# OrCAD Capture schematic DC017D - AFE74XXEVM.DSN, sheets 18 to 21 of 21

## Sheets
18 SHEET 17 - POWER SUPPLIES: size B; title: POWER SUPPLIES
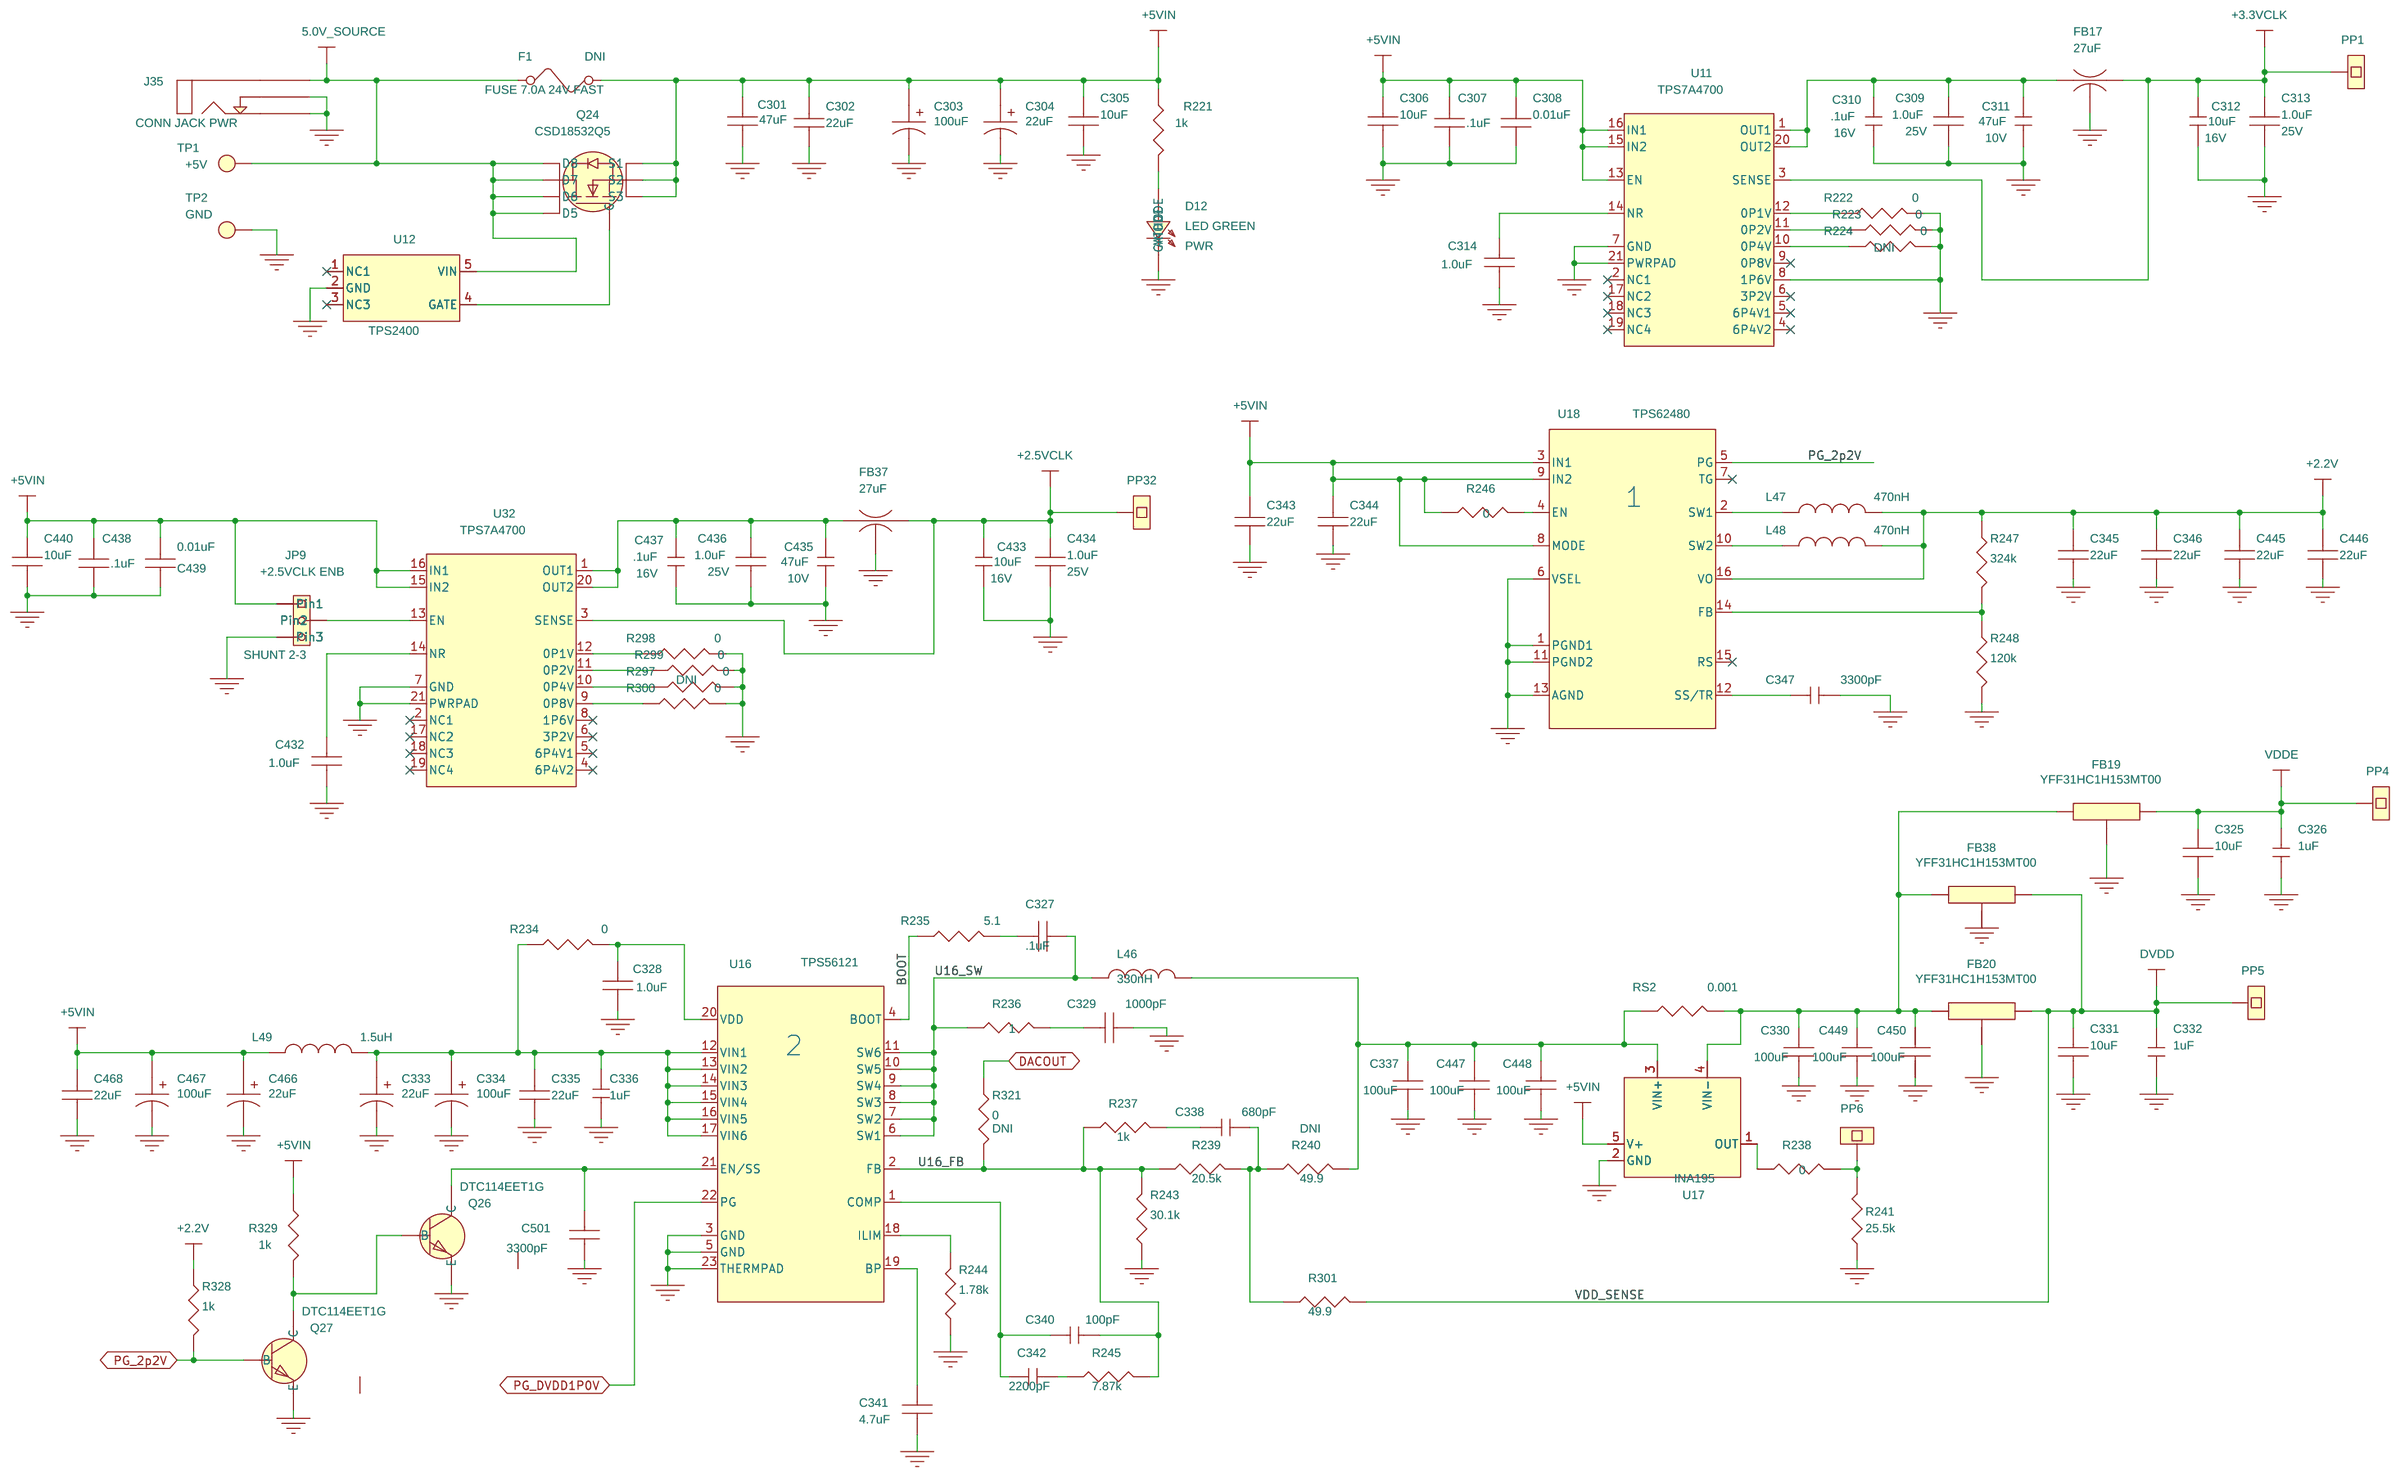
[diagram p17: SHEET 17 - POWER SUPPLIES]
19 SHEET 18 - POWER SUPPLIES: size B; title: POWER SUPPLIES +.9V, +1.8V
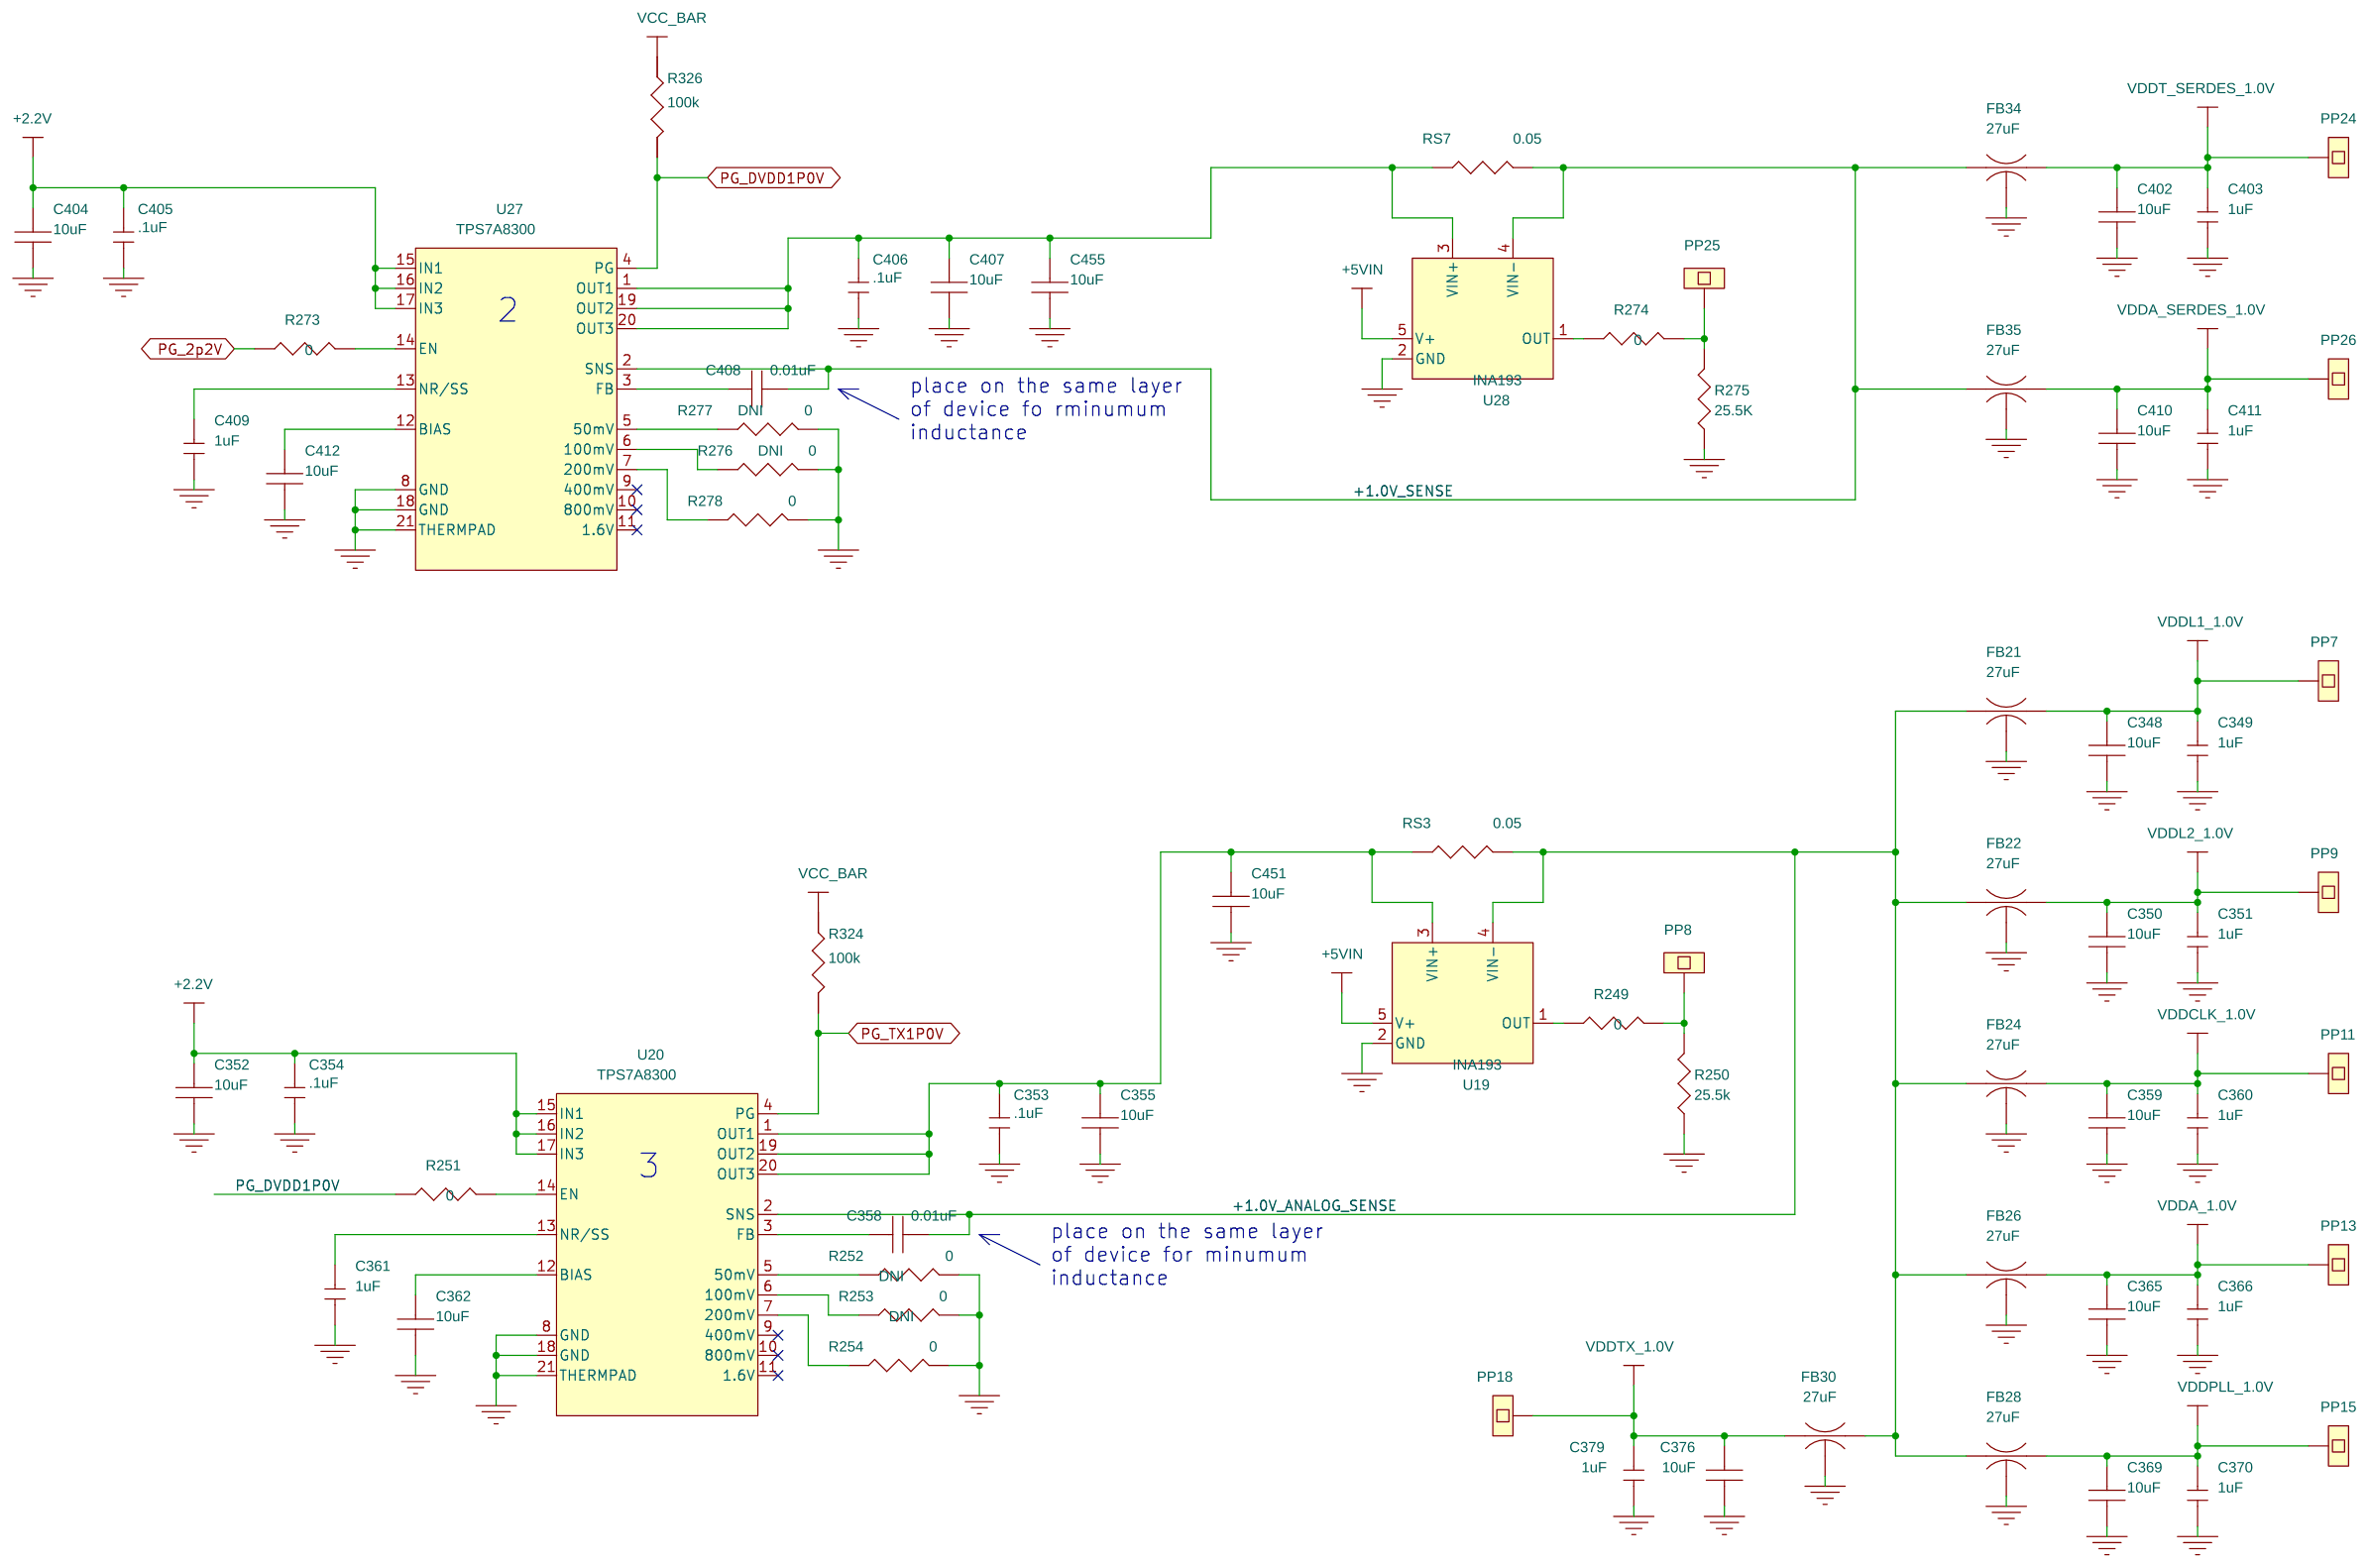
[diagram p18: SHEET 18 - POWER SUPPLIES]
20 SHEET 19 - POWER SUPPLIES: size B; title: POWER SUPPLIES +1.2V, +1.8V, +1.5V
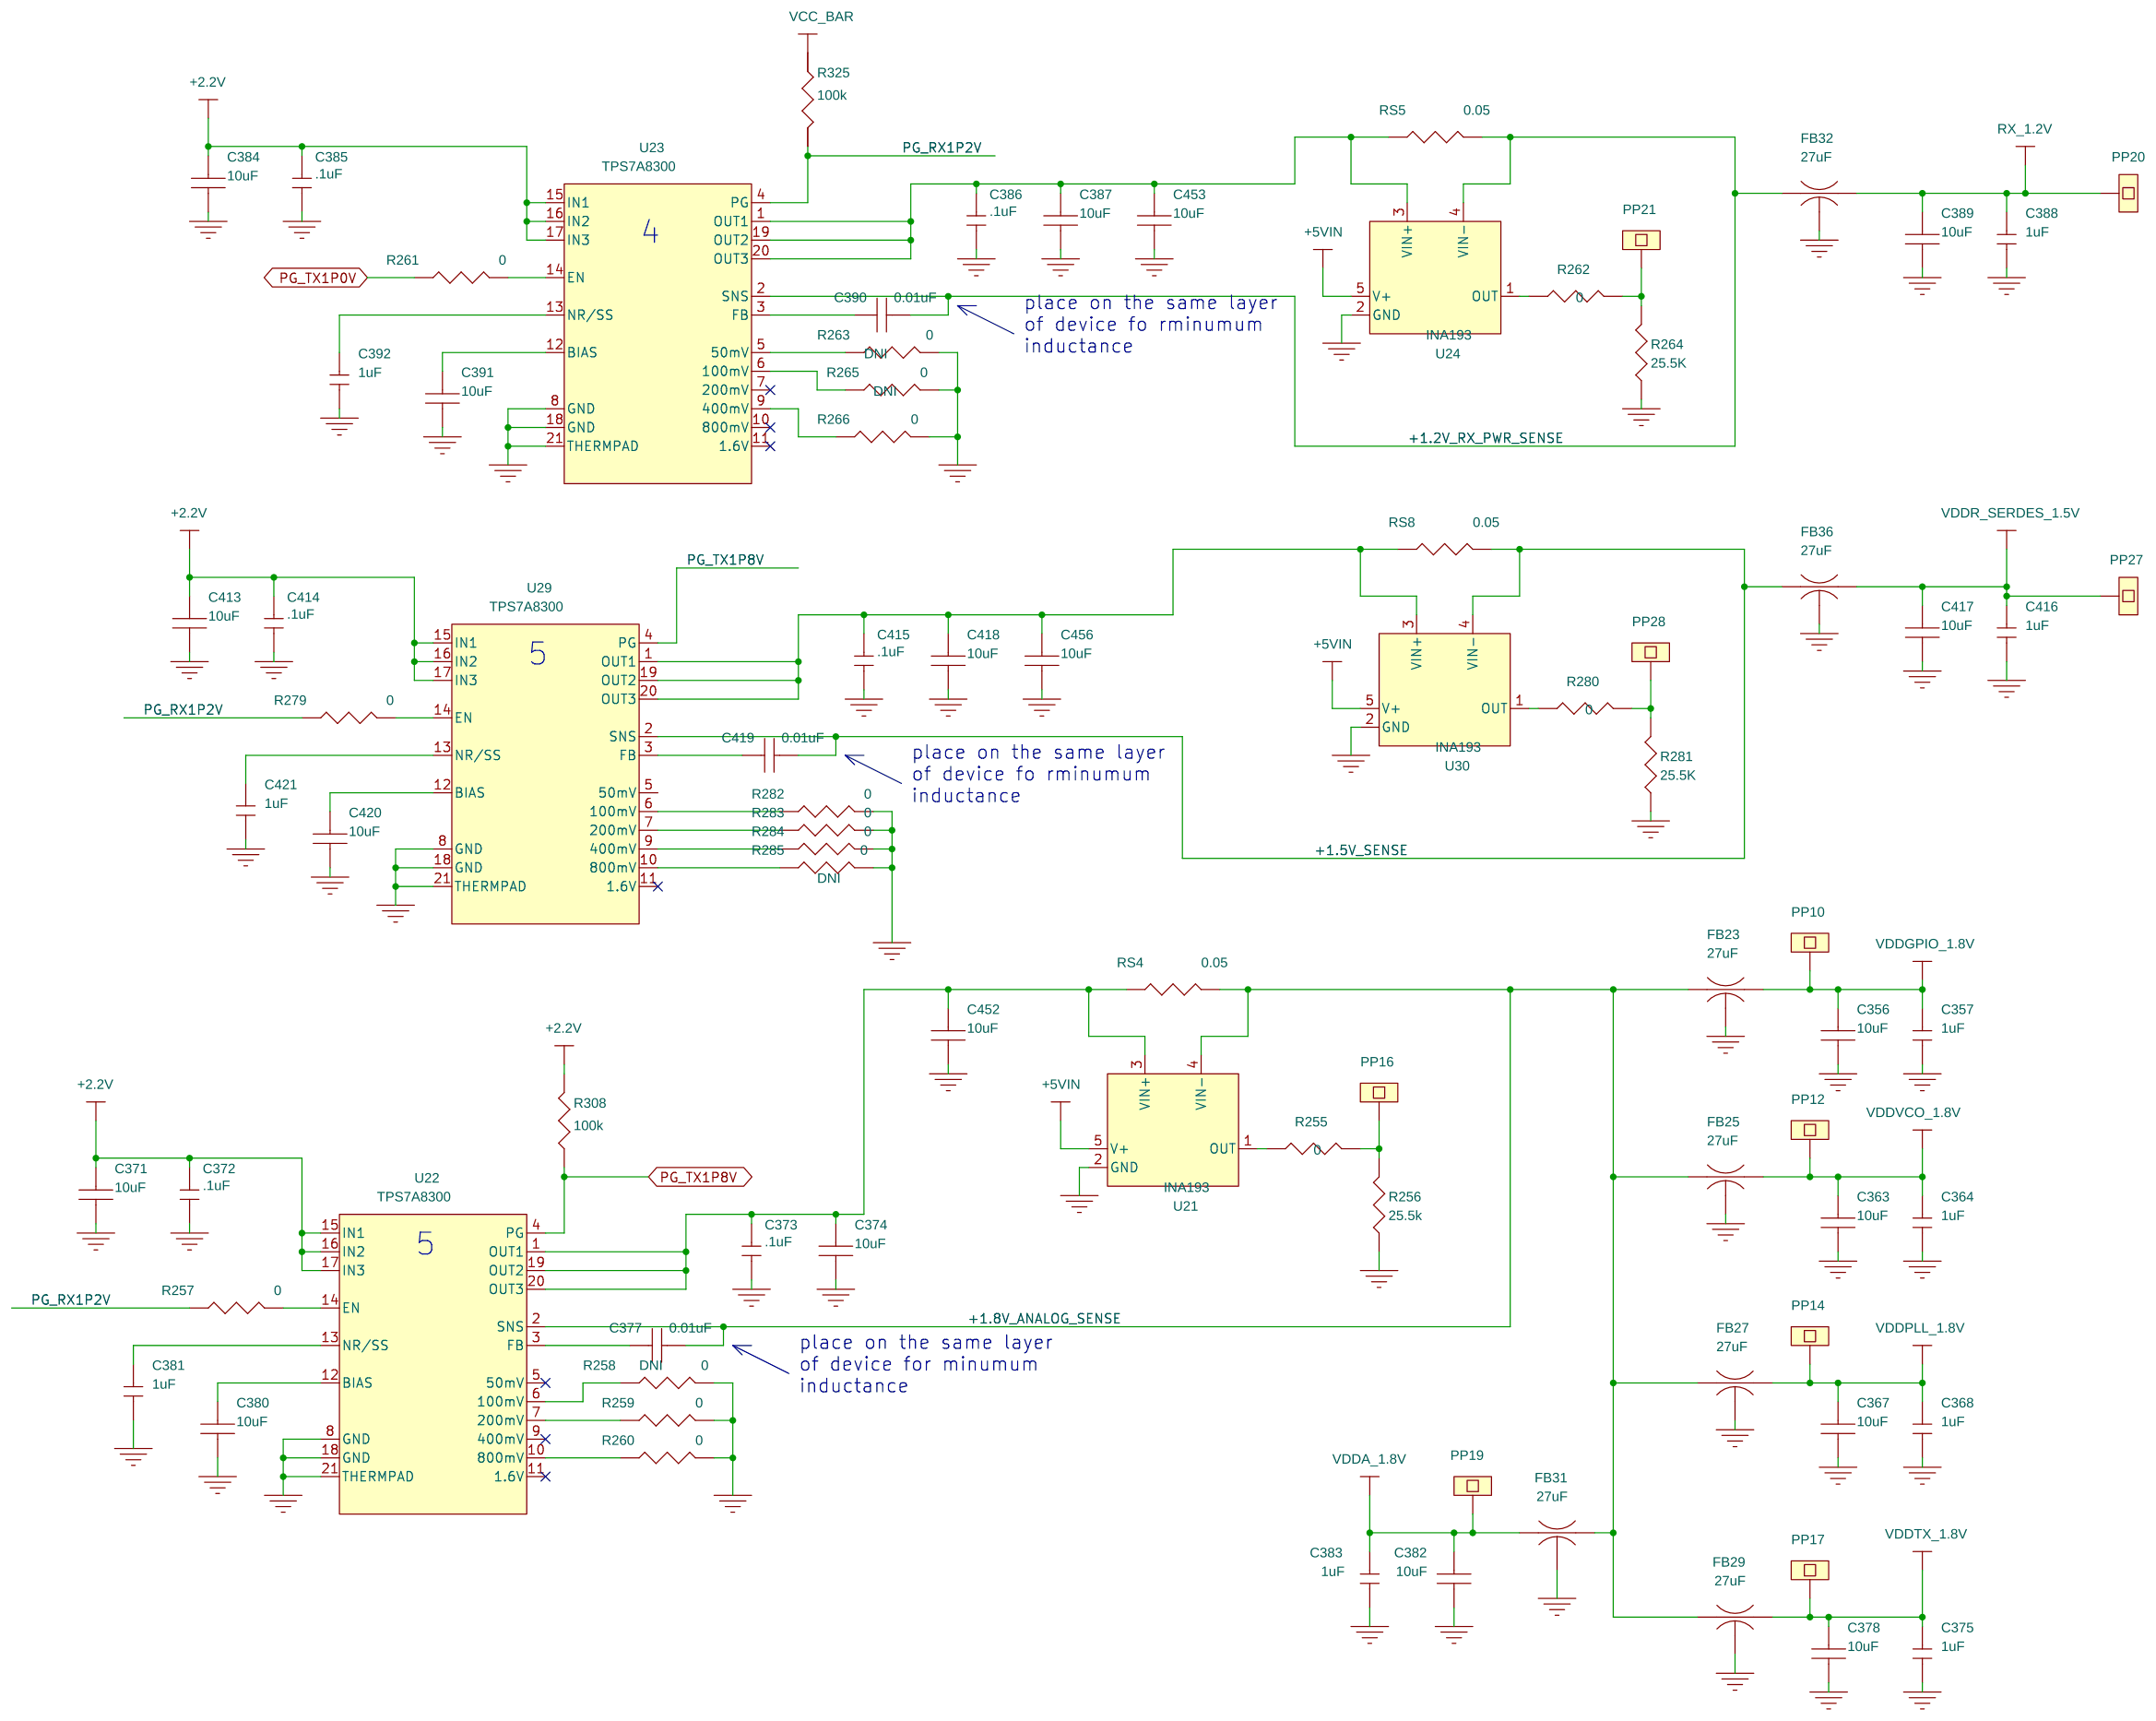
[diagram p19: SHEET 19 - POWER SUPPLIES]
21 SHEET 15 - USB I/F: size B; title: USB INTERFACE
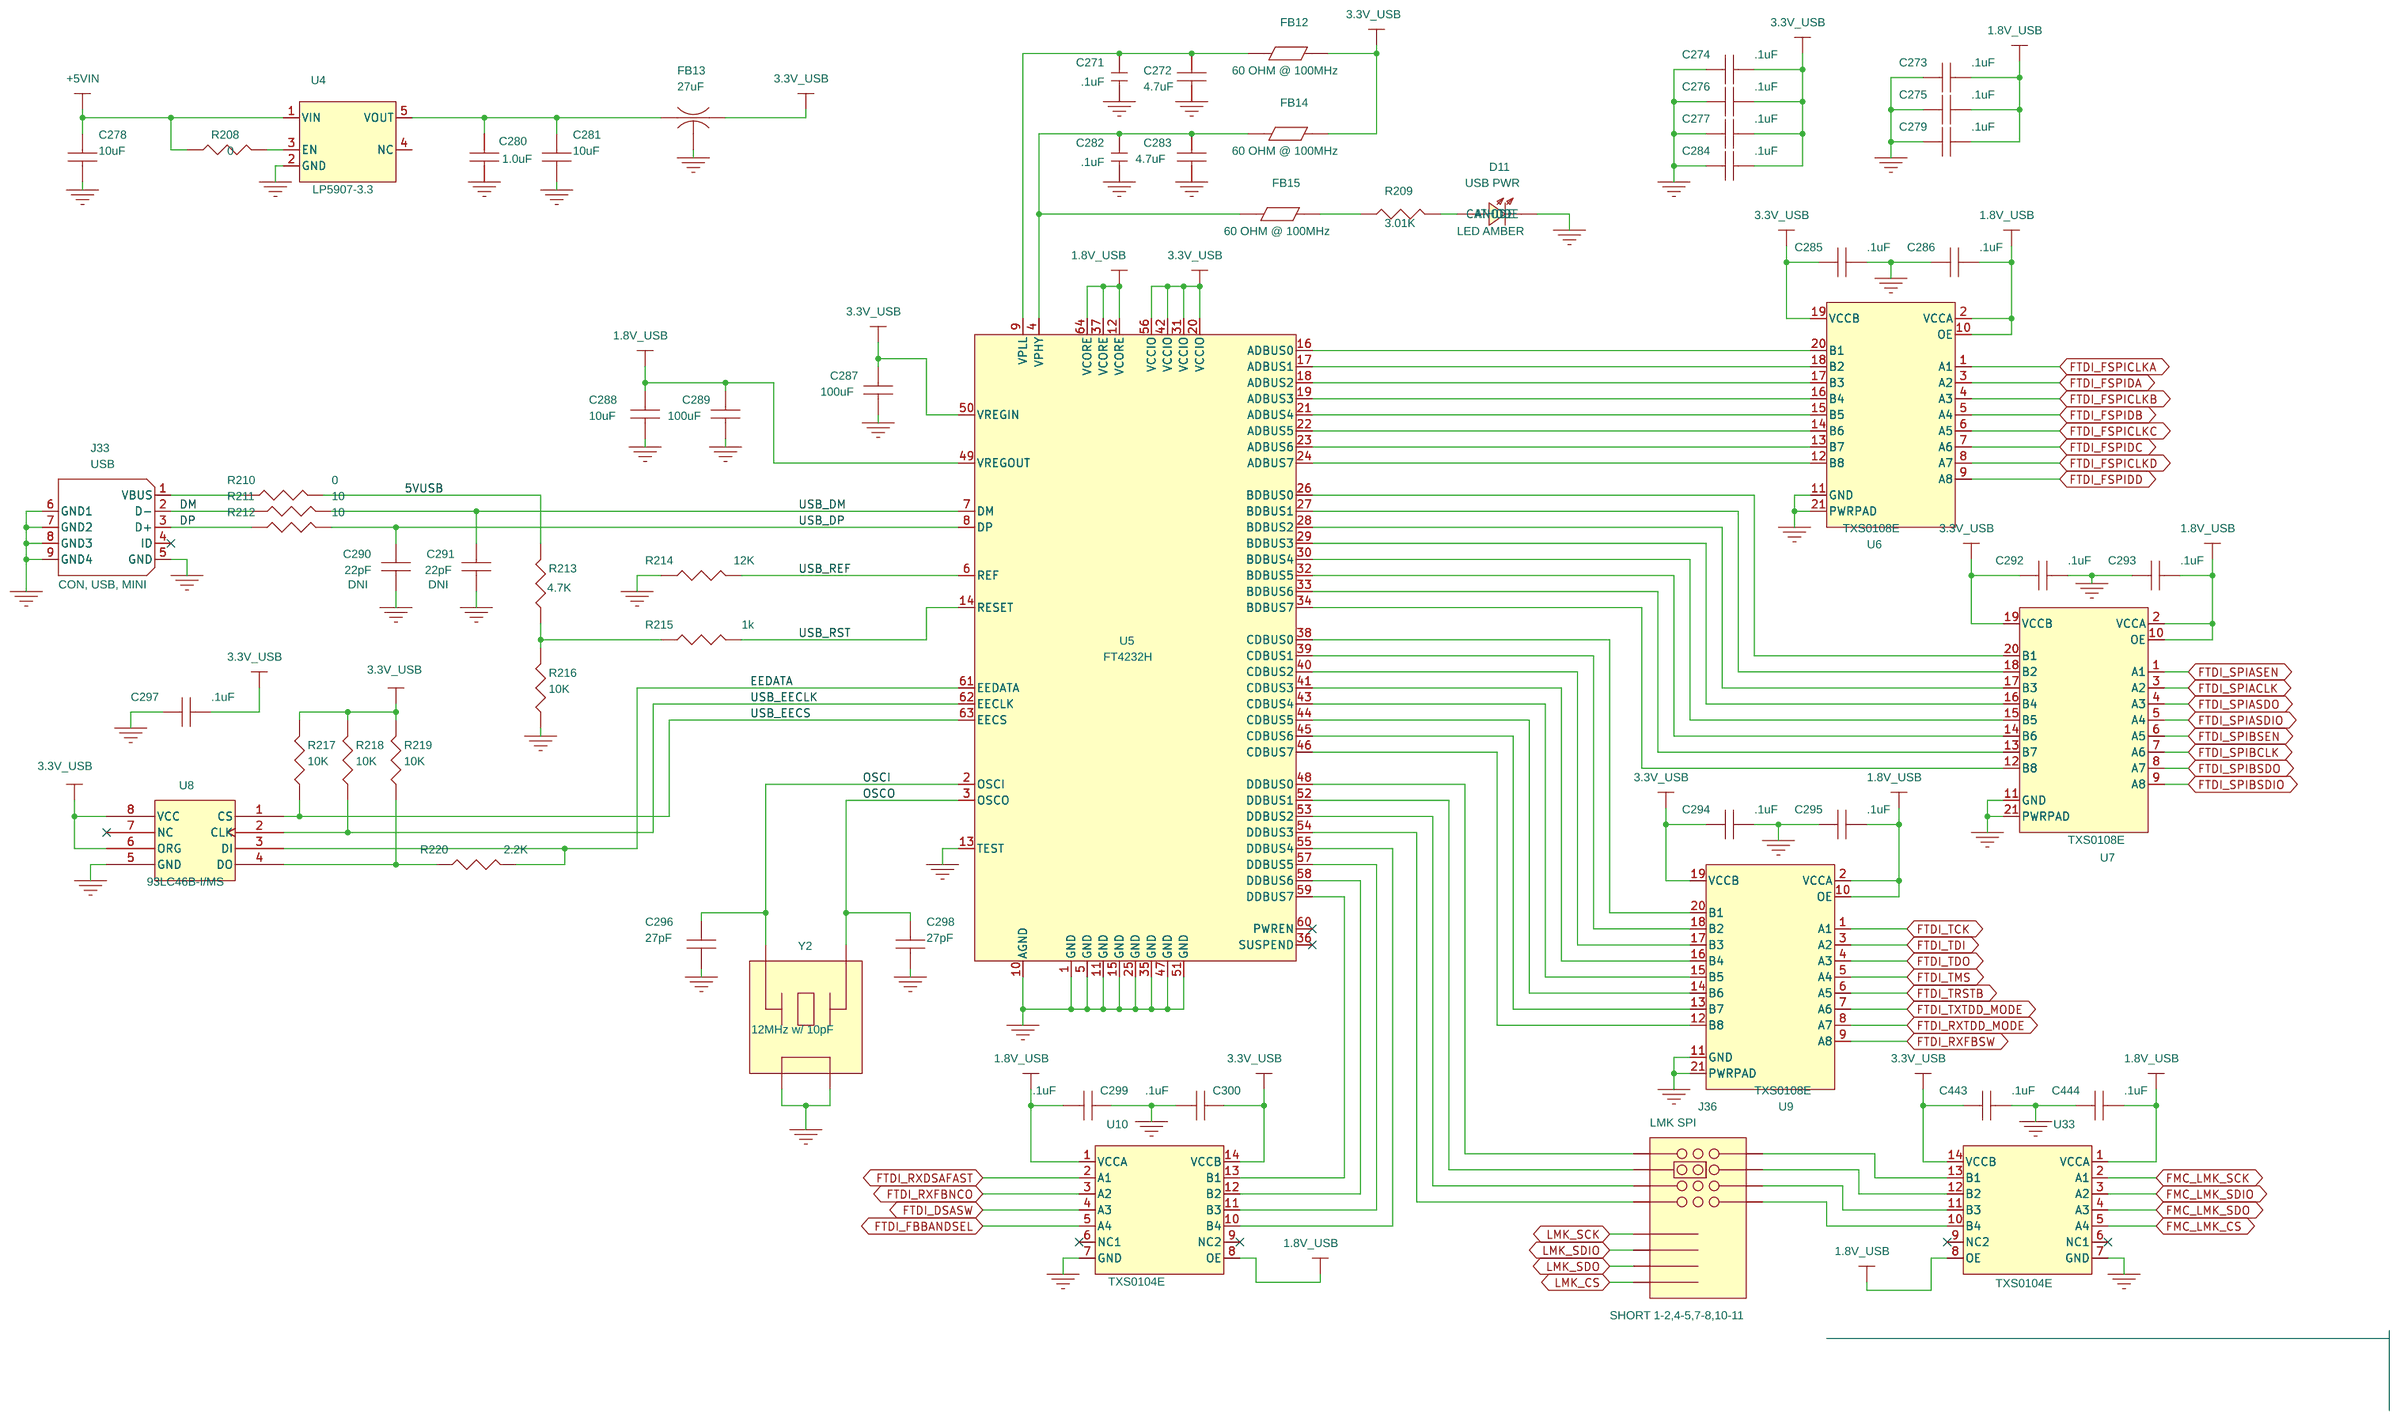
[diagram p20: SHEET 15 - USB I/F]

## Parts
sheet SHEET 15 - USB I/F
C271  .1uF  [0201]
C272  4.7uF  [0402]
C273  .1uF  [0402]
C274  .1uF  [0402]
C275  .1uF  [0402]
C276  .1uF  [0402]
C277  .1uF  [0402]
C278  10uF  [0805]
C279  .1uF  [0402]
C280  1.0uF  [0603]
C281  10uF  [0805]
C282  .1uF  [0201]
C283  4.7uF  [0402]
C284  .1uF  [0402]
C285  .1uF  [0402]
C286  .1uF  [0402]
C287  100uF  [1206]
C288  10uF  [1206]
C289  100uF  [1206]
C290  22pF  [0402]
C291  22pF  [0402]
C292  .1uF  [0402]
C293  .1uF  [0402]
C294  .1uF  [0402]
C295  .1uF  [0402]
C296  27pF  [0402]
C297  .1uF  [0402]
C298  27pF  [0402]
C299  .1uF  [0402]
C300  .1uF  [0402]
C443  .1uF  [0402]
C444  .1uF  [0402]
D11  LED AMBER  [LED_1206]
FB12  60 OHM @ 100MHz  [0603]
FB13  27uF  [1206_BEAD_NFM31P]
FB14  60 OHM @ 100MHz  [0603]
FB15  60 OHM @ 100MHz  [0603]
J33  CON, USB, MINI  [CON_SMRT_USBMINI_AB_F_mod]
J36  HEADER, 3X4, 100  [HDR_THVT_3x4_100_M]
R208  0  [0402]
R209  3.01K  [0402]
R210  0  [0402]
R211  10  [0402]
R212  10  [0402]
R213  4.7K  [0402]
R214  12K  [0402]
R215  1k  [0402]
R216  10K  [0402]
R217  10K  [0402]
R218  10K  [0402]
R219  10K  [0402]
R220  2.2K  [0402]
U4  LP5907-3.3  [DBV5]
U5  FT4232H  [LQFP_64_402x402_20]
U6  TXS0108E  [QFN_20_183x144_RGY]
U7  TXS0108E  [QFN_20_183x144_RGY]
U8  93LC46B-I/MS  [MSOP_8_118X118_26]
U9  TXS0108E  [QFN_20_183x144_RGY]
U10  TXS0104E  [TSSOP14]
U33  TXS0104E  [TSSOP14]
Y2  12MHz w/ 10pF  [XTAL_4_SM_130X102]
Z_SH-H61  SHUNT-HEADER
Z_SH-H62  SHUNT-HEADER
Z_SH-H63  SHUNT-HEADER
Z_SH-H64  SHUNT-HEADER
sheet SHEET 17 - POWER SUPPLIES
C301  47uF  [1210]
C302  22uF  [1206]
C303  100uF  [7343]
C304  22uF  [7343]
C305  10uF  [0805]
C306  10uF  [0805]
C307  .1uF  [0402]
C308  0.01uF  [0402]
C309  1.0uF  [0603]
C310  .1uF  [0402]
C311  47uF  [1210]
C312  10uF  [0805]
C313  1.0uF  [0603]
C314  1.0uF  [0603]
C325  10uF  [0508]
C326  1uF  [0306]
C327  .1uF  [0402]
C328  1.0uF  [0603]
C329  1000pF  [0402]
C330  100uF  [1206]
C331  10uF  [0508]
C332  1uF  [0306]
C333  22uF  [7343]
C334  100uF  [7343]
C335  22uF  [1206]
C336  1uF  [0306]
C337  100uF  [1206]
C338  680pF  [0402]
C340  100pF  [0402]
C341  4.7uF  [0603]
C342  2200pF  [0402]
C343  22uF  [1206]
C344  22uF  [1206]
C345  22uF  [1206]
C346  22uF  [1206]
C347  3300pF  [0402]
C432  1.0uF  [0603]
C433  10uF  [0805]
C434  1.0uF  [0603]
C435  47uF  [1210]
C436  1.0uF  [0603]
C437  .1uF  [0402]
C438  .1uF  [0402]
C439  0.01uF  [0402]
C440  10uF  [0805]
C445  22uF  [1206]
C446  22uF  [1206]
C447  100uF  [1206]
C448  100uF  [1206]
C449  100uF  [1206]
C450  100uF  [1206]
C466  22uF  [7343]
C467  100uF  [7343]
C468  22uF  [1206]
C501  3300pF  [0402]
D12  LED GREEN  [LED_1206]
F1  FUSE 7.0A 24V FAST  [1206]
FB17  27uF  [1206_BEAD_NFM31P]
FB19  YFF31HC1H153MT00  [FILTER_3_SM_YFF31HC]
FB20  YFF31HC1H153MT00  [FILTER_3_SM_YFF31HC]
FB37  27uF  [1206_BEAD_NFM31P]
FB38  YFF31HC1H153MT00  [FILTER_3_SM_YFF31HC]
J35  CONN JACK PWR  [CON_RAPC722_JACK_THVT_3]
JP9  HEADER_1x3_100  [HDR_THVT_1X3_100_M]
L46  330nH  [IND_SM_XAL60xx]
L47  470nH  [IND_0806]
L48  470nH  [IND_0806]
L49  1.5uH  [IND_SM_3020]
PP1  PROBE POINT  [PROBE_POINT_22PAD]
PP4  PROBE POINT  [PROBE_POINT_22PAD]
PP5  PROBE POINT  [PROBE_POINT_22PAD]
PP6  PROBE POINT  [PROBE_POINT_22PAD]
PP32  PROBE POINT  [PROBE_POINT_22PAD]
Q24  CSD18532Q5  [SON_Q5B_8]
Q26  DTC114EET1G  [SOT_416_3_63x31]
Q27  DTC114EET1G  [SOT_416_3_63x31]
R221  1k  [0402]
R222  0  [0402]
R223  0  [0402]
R224  0  [0402]
R234  0  [0402]
R235  5.1  [0402]
R236  1  [0402]
R237  1k  [0402]
R238  0  [0402]
R239  20.5k  [0402]
R240  49.9  [0402]
R241  25.5k  [0402]
R243  30.1k  [0402]
R244  1.78k  [0402]
R245  7.87k  [0402]
R246  0  [0402]
R247  324k  [0402]
R248  120k  [0402]
R297  0  [0402]
R298  0  [0402]
R299  0  [0402]
R300  0  [0402]
R301  49.9  [0402]
R321  0  [0402]
R328  1k  [0402]
R329  1k  [0402]
RS2  0.001  [2512]
SHN9  SHUNT HEADER
TP1  Testloop_Red  [testpoint_62dia]
TP2  Testloop_Black  [testpoint_62dia]
U11  TPS7A4700  [qfn20_rgw_p65pitch]
U12  TPS2400  [DBV5]
U16  TPS56121  [SON_DQP_22_PWRPAD]
U17  INA195  [DBV5]
U18  TPS62480  [QFN16_RNC]
U32  TPS7A4700  [qfn20_rgw_p65pitch]
sheet SHEET 18 - POWER SUPPLIES
C348  10uF  [0508]
C349  1uF  [0306]
C350  10uF  [0508]
C351  1uF  [0306]
C352  10uF  [0508]
C353  .1uF  [0204]
C354  .1uF  [0204]
C355  10uF  [0508]
C358  0.01uF  [0402]
C359  10uF  [0508]
C360  1uF  [0306]
C361  1uF  [0402]
C362  10uF  [0805]
C365  10uF  [0508]
C366  1uF  [0306]
C369  10uF  [0508]
C370  1uF  [0306]
C376  10uF  [0508]
C379  1uF  [0306]
C402  10uF  [0508]
C403  1uF  [0306]
C404  10uF  [0508]
C405  .1uF  [0204]
C406  .1uF  [0204]
C407  10uF  [0508]
C408  0.01uF  [0402]
C409  1uF  [0402]
C410  10uF  [0508]
C411  1uF  [0306]
C412  10uF  [0805]
C451  10uF  [0508]
C455  10uF  [0508]
FB21  27uF  [1206_BEAD_NFM31P]
FB22  27uF  [1206_BEAD_NFM31P]
FB24  27uF  [1206_BEAD_NFM31P]
FB26  27uF  [1206_BEAD_NFM31P]
FB28  27uF  [1206_BEAD_NFM31P]
FB30  27uF  [1206_BEAD_NFM31P]
FB34  27uF  [1206_BEAD_NFM31P]
FB35  27uF  [1206_BEAD_NFM31P]
PP7  PROBE POINT  [PROBE_POINT_22PAD]
PP8  PROBE POINT  [PROBE_POINT_22PAD]
PP9  PROBE POINT  [PROBE_POINT_22PAD]
PP11  PROBE POINT  [PROBE_POINT_22PAD]
PP13  PROBE POINT  [PROBE_POINT_22PAD]
PP15  PROBE POINT  [PROBE_POINT_22PAD]
PP18  PROBE POINT  [PROBE_POINT_22PAD]
PP24  PROBE POINT  [PROBE_POINT_22PAD]
PP25  PROBE POINT  [PROBE_POINT_22PAD]
PP26  PROBE POINT  [PROBE_POINT_22PAD]
R249  0  [0402]
R250  25.5k  [0402]
R251  0  [0402]
R252  0  [0402]
R253  0  [0402]
R254  0  [0402]
R273  0  [0402]
R274  0  [0402]
R275  25.5K  [0402]
R276  0  [0402]
R277  0  [0402]
R278  0  [0402]
R324  100k  [0402]
R326  100k  [0402]
RS3  0.05  [0805]
RS7  0.05  [0805]
U19  INA193  [DBV5]
U20  TPS7A8300  [qfn20_rgw_p65pitch]
U27  TPS7A8300  [qfn20_rgw_p65pitch]
U28  INA193  [DBV5]
sheet SHEET 19 - POWER SUPPLIES
C356  10uF  [0508]
C357  1uF  [0306]
C363  10uF  [0508]
C364  1uF  [0306]
C367  10uF  [0508]
C368  1uF  [0306]
C371  10uF  [0508]
C372  .1uF  [0204]
C373  .1uF  [0204]
C374  10uF  [0508]
C375  1uF  [0306]
C377  0.01uF  [0402]
C378  10uF  [0508]
C380  10uF  [0805]
C381  1uF  [0402]
C382  10uF  [0508]
C383  1uF  [0306]
C384  10uF  [0508]
C385  .1uF  [0204]
C386  .1uF  [0204]
C387  10uF  [0508]
C388  1uF  [0306]
C389  10uF  [0508]
C390  0.01uF  [0402]
C391  10uF  [0805]
C392  1uF  [0402]
C413  10uF  [0508]
C414  .1uF  [0204]
C415  .1uF  [0204]
C416  1uF  [0306]
C417  10uF  [0508]
C418  10uF  [0508]
C419  0.01uF  [0402]
C420  10uF  [0805]
C421  1uF  [0402]
C452  10uF  [0508]
C453  10uF  [0508]
C456  10uF  [0508]
FB23  27uF  [1206_BEAD_NFM31P]
FB25  27uF  [1206_BEAD_NFM31P]
FB27  27uF  [1206_BEAD_NFM31P]
FB29  27uF  [1206_BEAD_NFM31P]
FB31  27uF  [1206_BEAD_NFM31P]
FB32  27uF  [1206_BEAD_NFM31P]
FB36  27uF  [1206_BEAD_NFM31P]
PP10  PROBE POINT  [PROBE_POINT_22PAD]
PP12  PROBE POINT  [PROBE_POINT_22PAD]
PP14  PROBE POINT  [PROBE_POINT_22PAD]
PP16  PROBE POINT  [PROBE_POINT_22PAD]
PP17  PROBE POINT  [PROBE_POINT_22PAD]
PP19  PROBE POINT  [PROBE_POINT_22PAD]
PP20  PROBE POINT  [PROBE_POINT_22PAD]
PP21  PROBE POINT  [PROBE_POINT_22PAD]
PP27  PROBE POINT  [PROBE_POINT_22PAD]
PP28  PROBE POINT  [PROBE_POINT_22PAD]
R255  0  [0402]
R256  25.5k  [0402]
R257  0  [0402]
R258  0  [0402]
R259  0  [0402]
R260  0  [0402]
R261  0  [0402]
R262  0  [0402]
R263  0  [0402]
R264  25.5K  [0402]
R265  0  [0402]
R266  0  [0402]
R279  0  [0402]
R280  0  [0402]
R281  25.5K  [0402]
R282  0  [0402]
R283  0  [0402]
R284  0  [0402]
R285  0  [0402]
R308  100k  [0402]
R325  100k  [0402]
RS4  0.05  [0805]
RS5  0.05  [0805]
RS8  0.05  [0805]
U21  INA193  [DBV5]
U22  TPS7A8300  [qfn20_rgw_p65pitch]
U23  TPS7A8300  [qfn20_rgw_p65pitch]
U24  INA193  [DBV5]
U29  TPS7A8300  [qfn20_rgw_p65pitch]
U30  INA193  [DBV5]

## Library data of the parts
C271 C282 = CAP0402_0: Mfr_Name: MURATA; Mfr_Part_Number: GRM033R61A104KE15D; TOL: 10%; Voltage: 10V
C272 C283 = CAP_NP_0: Mfr_Name: TDK; Mfr_Part_Number: C1005X5R1A475M050BC; TOL: 20%; VOLTAGE: 10V
C273-C277 C279 C284-C286 C292-C295 C297 C299 C300 C307 C327 C438 C443 C444 = CAPACITOR_NP_1: Mfr_Name: MURATA; Mfr_Part_Number: GCM155R71C104KA55D; TOL: 10%; Voltage: 16V
C278 C281 C305 C362 C380 C391 C412 C420 = CAP_NP_1: Mfr_Name: SAMSUNG; Mfr_Part_Number: CL21B106KOQNNNE; TOL: 10%; VOLTAGE: 16V
C280 C314 C432 = CAP_NP_0: Mfr_Name: TKD CORP; Mfr_Part_Number: CGJ3E1X7R1E105K080AC; TOL: 10%; VOLTAGE: 25V
C287 = CAP_1206: Mfr_Name: KEMET; Mfr_Part_Number: C1206C107M9PACTU
C288 = CAP_NP_1: CLASS: DISCRETE; Mfr_Name: MURATA; Mfr_Part_Number: GJ831CR61E106KE83L; TOL: 10%; VOLTAGE: 25V
C289 C330 C337 C447-C450 = CAP_1206: Mfr_Name: TDK; Mfr_Part_Number: C3216X5R1A107M160AC
C290 C291 = CAP_NP: Mfr_Name: AVX; Mfr_Part_Number: 04025A220KAT2A; Note: DNI; TOL: 10%; VOLTAGE: 50V
C296 C298 = CAP_NP: GROUP: NOT INSTALLED; Mfr_Name: AVX; Mfr_Part_Number: 04025U270GAT2A; TOL: 5%; VOLTAGE: 50V
D11 = LED_AMBER_1206: TI_SILKTEXT: USB PWR
FB12 FB14 FB15 = FERRITE_BEAD: Mfr_Name: Taiyo Yuden; Mfr_Part_Number: BKP1608HS600-T
FB13 FB17 FB21-FB32 FB34-FB37 = BEAD_NFM31P: Mfr_Name: Murata; Mfr_Part_Number: NFM31PC276B0J3L; Tolerance: 20%
J33 = USB_MINI_AB_MNE20-5G5P10: Mfr_Name: Molex; Mfr_Part_Number: 0678038020; TI_SILKTEXT: USB
J36 = HEADER_3x4_100: Mfr_Part_Number: HTSW-104-07-G-T; Note: SHORT 1-2,4-5,7-8,10-11; TI_SILKTEXT: LMK SPI
R208 R210 R222 R223 R234 R238 R246 R249 R251 R254 R255 R257 R259-R262 R266 R273 R274 R278-R280 R282-R284 R298-R300 = R: Mfr_Name: Panasonic; Mfr_Part_Number: ERJ-2GE0R00X; TOL: 5%
R209 = R: Mfr_Name: PANASONIC; Mfr_Part_Number: ERJ-2RKF3011X; TOL: 5%; VOLTAGE: 1/16W
R211 R212 = Res_0402_10_H
R213 = RESISTOR: 10K ohm, +/-1%, 1/16W(0402); Mfr_Name: PANASONIC; Mfr_Part_Number: ERJ-2RKF4701X; Package: SMD; Terasic_Prt: M0597; Type: Resistor
R214 = R: Mfr_Name: PANASONIC; Mfr_Part_Number: ERJ-2RKF1202X; TOL: 1%; Wattage: 1/16W
R215 = R_0: Mfr_Name: PANASONIC; Mfr_Part_Number: ERJ-2RKF1001X; TOL: 1%
R216-R219 R248 = R_0: CLASS: DISCRETE; Mfr_Name: PANASONIC; Mfr_Part_Number: ERJ-2RKF1002X; TOL: 1%
R220 = RESISTOR: 2.2K ohm, +/-1%, 1/16W(0402); Mfr_Name: Yageo; Mfr_Part_Number: RC0402FR-072K2L; Package: SMD; Terasic_Prt: M0733; Type: Resistor
U4 = LP5907: Mfr_Name: Texas Instruments; Mfr_Part_Number: LP5907MFX-3.3/NOPB
U5 = FT4232H_2: Mfr_Part_Number: FT4232HL-REEL
U6 U7 U9 = TXS0108E
U8 = EEPROM: 93LC46B-I/SN,Serial EEPROM, 64 x 16bit, 2.5V-5.5V; Mfr_Name: Microchip; Package: SMD; Terasic_Prt: M0252
U10 U33 = TXS0104E: Mfr_Name: Texas Instruments; Mfr_Part_Number: TXS0104EPWR
Y2 = CRYSTAL1-4_SM: Mfr_Name: Abracon; Mfr_Part_Number: ABM8G-12.000MHZ-B4Y-T
Z_SH-H61-Z_SH-H64 = SHUNT-2PINHEADER: Mfr_Name: TE CONNECTIVITY; Mfr_Part_Number: 1-382811-6
C301 = CAP_NP_0: Mfr_Name: MURATA; Mfr_Part_Number: GRM32ER71A476KE15L; TOL: 10%; VOLTAGE: 10V
C302 C335 C343-C346 C445 C446 C468 = CAP_1210_22uF: Mfr_Name: MURATA; Mfr_Part_Number: GRM31CR71A226KE15L
C303 C334 C467 = CAP_POL: Mfr_Name: AVX; Mfr_Part_Number: TCJY107M010R0045
C304 C333 C466 = CAP_POL: Mfr_Name: AVX; Mfr_Part_Number: TPSD226M025R0100
C306 C440 = CAP_NP_1: Mfr_Name: MURATA; Mfr_Part_Number: GRM21BR61E106KA73L; TOL: 10%; VOLTAGE: 25V
C308 C439 = CAPACITOR_NP_1: Mfr_Name: MURATA; Mfr_Part_Number: GCM155R71H103KA55J; TOL: 10%; Voltage: 50V
C309 C313 C434 C436 = CAP_NP_1: Mfr_Name: TKD CORP; Mfr_Part_Number: CGJ3E1X7R1E105K080AC; TOL: 10%; VOLTAGE: 25V
C310 C437 = CAP0603: Mfr_Name: MURATA; Mfr_Part_Number: GCM155R71C104KA55D; TOL: 10%; Voltage: 16V
C311 C435 = CAP0201_0: Mfr_Name: MURATA; Mfr_Part_Number: GRM32ER61A476KE20L; TOL: 10%; VOLTAGE: 10V
C312 C433 = CAP0201_0: Mfr_Name: TDK; Mfr_Part_Number: C2012X5R1C106K085AC; TOL: 10%; VOLTAGE: 16V
C325 C331 C348 C350 C352 C355 C356 C359 C363 C365 C367 C369 C371 C374 C376 C378 C382 C384 C387 C389 C402 C404 C407 C410 C413 C417 C418 C451-C453 C455 C456 = CAP_NP_1: Mfr_Name: Taiyo Yuden; Mfr_Part_Number: LWK212BJ106MD-T; TOL: 20%; VOLTAGE: 10V
C326 C332 C336 C349 C351 C357 C360 C364 C366 C368 C370 C375 C379 C383 C388 C403 C411 C416 = CAP0201_0: CLASS: DISCRETE; Mfr_Name: Samsung; Mfr_Part_Number: C0816X5R1C105M050AC; TOL: 20%; VOLTAGE: 16V
C328 = CAP_NP_0: Mfr_Name: Samsung Electro-Mechanics America, Inc; Mfr_Part_Number: CL10B105KO8NNNC; TOL: 10%; VOLTAGE: 16V
C329 = CAPACITOR_NP_1: Mfr_Name: MURATA; Mfr_Part_Number: GRM155R71H102KA01D; TOL: 10%; Voltage: 16V
C338 = CAP_0402_2200pF_H: Mfr_Name: Murata; Mfr_Part_Number: GRM155R72A681KA01D
C340 = CAP_0402_2200pF_H: Mfr_Name: Murata; Mfr_Part_Number: GCM1555C1H101JA16D
C341 = CAP_NP_0: Mfr_Name: Kemet; Mfr_Part_Number: C0603C475K8PACTU; TOL: 10%; VOLTAGE: 10V
C342 = CAP_0402_2200pF_H: Mfr_Name: Murata; Mfr_Part_Number: GCM155R71H222KA37D
C347 = CAP_0402_2200pF_H: Mfr_Name: SAMSUNG; Mfr_Part_Number: CL05B332JB5NNNC
C501 = CAPACITOR_NP_1: Mfr_Name: SAMSUNG; Mfr_Part_Number: CL05B332JB5NNNC; TOL: 10%; Voltage: 16V
D12 = LED_GREEN_1206: TI_SILKTEXT: PWR
F1 = FUSE_0: Mfr_Name: Littlefuse Inc.; Mfr_Part_Number: RF2329-000; Note: DNI
FB19 FB20 FB38 = FILTER_YFF31HC: Mfr_Part_Number: YFF31HC1H153MT000N
J35 = CONN_JACK_PWR: Mfr_Name: SWITCHCRAFT; Mfr_Part_Number: RAPC722X
JP9 = HEADER_3: Mfr_Name: Samtec; Mfr_Part_Number: HTSW-103-07-G-S; Note: SHUNT 2-3; TI_Silktext: +2.5VCLK ENB
L46 = CHOKE: Mfr_Name: Coilcraft; Mfr_Part_Number: XAL6030-331ME
L47 L48 = CHOKE: Mfr_Name: Murata; Mfr_Part_Number: DFE201612P-R47M=P2
L49 = CHOKE: Mfr_Name: Wurth; Mfr_Part_Number: 74438336015
PP1 PP32 = PROBE_POINT_0: Mfr_Name: Harwin; Mfr_Part_Number: P1113SS3; Note: DNI; TI_Silktext: +3.3VCLK
PP4 PP5 = PROBE_POINT_0: Mfr_Name: Harwin; Mfr_Part_Number: P1113SS3; Note: DNI; TI_Silktext: +0.9V_VDD
PP6 PP8 PP16 PP21 PP25 PP28 = PROBE_POINT_0: Mfr_Name: Harwin; Mfr_Part_Number: P1113SS3; Note: DNI; TI_Silktext: <TI_Silktext>
Q24 = CSD18532Q5B: Mfr_Name: Texas Instruments
Q26 Q27 = MMBT2222A: Mfr_Name: ON Semiconductor
R221 = Res_0402_1k
R224 R252 R253 R258 R263 R265 R276 R277 R285 R297 R321 = R: Mfr_Name: Panasonic; Mfr_Part_Number: ERJ-2GE0R00X; Note: DNI; TOL: 5%
R235 = R: Mfr_Name: Samsung; Mfr_Part_Number: RC1005F5R1CS; TOL: 1%
R236 = R: Mfr_Name: VISHAY DALE; Mfr_Part_Number: CRCW04021R00FKEDHP; TOL: 1%
R237 = R: Mfr_Name: Panasonic; Mfr_Part_Number: ERJ-2RKF1001X; TOL: 1%
R239 = R: Mfr_Name: Panasonic; Mfr_Part_Number: ERJ-2RKF2052X; TOL: 1%
R240 = R: Mfr_Name: Panasonic; Mfr_Part_Number: ERJ-2RKF49R9X; Note: DNI; TOL: 1%
R241 R250 R256 R264 R275 R281 = R_1: CLASS: DISCRETE; Mfr_Name: Vishay Dale; Mfr_Part_Number: CRCW040225K5FKED; TOL: 1%
R243 = R: Mfr_Name: Panasonic; Mfr_Part_Number: ERJ-2RKF3012X; TOL: 1%
R244 = R: Mfr_Name: Panasonic; Mfr_Part_Number: ERJ-2RKF1781X; TOL: 1%
R245 = R: Mfr_Name: Panasonic; Mfr_Part_Number: ERJ-2RKF7871X; TOL: 1%
R247 = R_0: CLASS: DISCRETE; Mfr_Name: PANASONIC; Mfr_Part_Number: ERJ-2RKF3243X; TOL: 1%
R301 = R: Mfr_Name: Panasonic; Mfr_Part_Number: ERJ-2RKF49R9X; TOL: 1%
R328 = R_1: CLASS: DISCRETE; Mfr_Name: Panasonic; Mfr_Part_Number: ERJ-2RKF1001X; TOL: 1%
R329 = R_0: Mfr_Name: Panasonic; Mfr_Part_Number: ERJ-2RKF1001X; PART_NUMBER: Panasonic ERJ-2RKF1001X; TOL: 1%
RS2 = R: Mfr_Name: Panasonic; Mfr_Part_Number: ERJ-M1WTF1M0U; Note: Rs; TOL: 1%
SHN9 = SHUNT_HEADER: Mfr_Name: TE CONNECTIVITY; Mfr_Part_Number: 1-382811-6
TP1 = TESTLOOP_BLACK: Mfr_Name: Keystone; Mfr_Part_Number: 5010; TI_SILKTEXT: +5V
TP2 = TESTLOOP_BLACK: Mfr_Name: KEYSTONE; Mfr_Part_Number: 5011; TI_SILKTEXT: GND
U11 U32 = TPS7A4700: Mfr_Name: Texas Instruments; Mfr_Part_Number: TPS7A4700RGWT
U12 = TPS2400: Mfr_Name: Texas Instruments; Mfr_Part_Number: TPS2400DBVT
U16 = TPS56121: Mfr_Name: Texas Instruments; Mfr_Part_Number: TPS56121DQPT
U17 = INA138: Mfr_Name: Texas Instruments; Mfr_Part_Number: INA195AIDBVT
U18 = TPS62480_VQFN16: Mfr_Part_Number: TPS62480RNCT
C353 C354 C372 C373 C385 C386 C405 C406 C414 C415 = CAP0402_0: Mfr_Name: Murata; Mfr_Part_Number: LLL153C80J104ME01E; TOL: 20%; Voltage: 6.3V
C358 C377 C390 C408 C419 = CAP_NP_1: Mfr_Name: MURATA; Mfr_Part_Number: GCM155R71H103KA55J; TOL: 10%; VOLTAGE: 50V
C361 C381 C392 C409 C421 = CAP0201_0: CLASS: DISCRETE; Mfr_Name: Murata; Mfr_Part_Number: GRM153R61A105ME95D; TOL: 10%; VOLTAGE: 10V
PP7 = PROBE_POINT_0: Mfr_Name: Harwin; Mfr_Part_Number: P1113SS3; Note: DNI; TI_Silktext: +0.9V_VDDL1
PP9 = PROBE_POINT_0: Mfr_Name: Harwin; Mfr_Part_Number: P1113SS3; Note: DNI; TI_Silktext: +0.9V_VDDL2
PP11 = PROBE_POINT_0: Mfr_Name: Harwin; Mfr_Part_Number: P1113SS3; Note: DNI; TI_Silktext: +0.9V_VDDCLK
PP13 = PROBE_POINT_0: Mfr_Name: Harwin; Mfr_Part_Number: P1113SS3; Note: DNI; TI_Silktext: +0.9V_VDDA
PP15 PP17 PP18 = PROBE_POINT_0: Mfr_Name: Harwin; Mfr_Part_Number: P1113SS3; Note: DNI; TI_Silktext: +0.9V_VDDPLL
PP20 PP24 PP26 = PROBE_POINT_0: Mfr_Name: Harwin; Mfr_Part_Number: P1113SS3; Note: DNI; TI_Silktext: +1.8V_VDDIO
R324-R326 = R_1: CLASS: DISCRETE; Mfr_Name: Panasonic; Mfr_Part_Number: ERJ-2RKF1003X; TOL: 1%
RS3-RS5 RS7 RS8 = R: Mfr_Name: Vishay Dale; Mfr_Part_Number: WSL0805R0500FEA18; Note: Rs; TOL: 1%
U19 U21 U24 U28 U30 = INA138: Mfr_Name: Texas Instruments; Mfr_Part_Number: INA193AIDBVT
U20 U22 U23 U27 U29 = TPS7A8300: Mfr_Part_Number: TPS7A8300RGWR
PP10 PP12 = PROBE_POINT_0: Mfr_Name: Harwin; Mfr_Part_Number: P1113SS3; Note: DNI; TI_Silktext: +1.8V_VDDVCO
PP14 = PROBE_POINT_0: Mfr_Name: Harwin; Mfr_Part_Number: P1113SS3; Note: DNI; TI_Silktext: +1.8V_VDDAPLL
PP19 = PROBE_POINT_0: Mfr_Name: Harwin; Mfr_Part_Number: P1113SS3; Note: DNI; TI_Silktext: +1.8V_VDDR
PP27 = PROBE_POINT_0: Mfr_Name: Harwin; Mfr_Part_Number: P1113SS3; Note: DNI; TI_Silktext: +1.8V_VDDA
R308 = R: Mfr_Name: Panasonic; Mfr_Part_Number: ERJ-2RKF1003X; TOL: 1%

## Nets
1.8V_USB: C273.2 C275.2 C279.2 C286.2 C288.1 C289.1 C293.2 C295.2 C299.2 C444.2 U5.12(VCORE) U5.37(VCORE) U5.49(VREGOUT) U5.64(VCORE) U6.2(VCCA) U6.10(OE) U7.2(VCCA) U7.10(OE) U9.2(VCCA) U9.10(OE) U10.1(VCCA) U10.8(OE) U33.1(VCCA) U33.8(OE)
3.3V_USB: C274.2 C276.2 C277.2 C284.2 C285.1 C287.1 C292.1 C294.1 C297.2 C300.1 C443.1 FB12.1 FB13.3 FB14.1 R217.2 R218.2 R219.2 U5.20(VCCIO) U5.31(VCCIO) U5.42(VCCIO) U5.50(VREGIN) U5.56(VCCIO) U6.19(VCCB) U7.19(VCCB) U8.6(ORG) U8.8(VCC) U9.19(VCCB) U10.14(VCCB) U33.14(VCCB)
5.0V_SOURCE: F1.1 J35.1 Q24.5(D5) Q24.6(D6) Q24.7(D7) Q24.8(D8) TP1.1(TP) U12.5(VIN)
5VUSB: R210.1 R213.1
+1.0V_ANALOG_SENSE: C358.2 FB21.1 FB22.1 FB24.1 FB26.1 FB28.1 FB30.1 RS3.1 U19.4(VIN-) U20.2(SNS)
+1.0V_SENSE: C408.2 FB34.1 FB35.1 RS7.1 U27.2(SNS) U28.4(VIN-)
+1.2V_RX_PWR_SENSE: C390.2 FB32.1 RS5.1 U23.2(SNS) U24.4(VIN-)
+1.5V_SENSE: C419.2 FB36.1 RS8.1 U29.2(SNS) U30.4(VIN-)
+1.8V_ANALOG_SENSE: C377.2 FB23.1 FB25.1 FB27.1 FB29.3 FB31.1 RS4.1 U21.4(VIN-) U22.2(SNS)
+2.2V: C345.2 C346.2 C352.1 C354.1 C371.1 C372.1 C384.1 C385.1 C404.1 C405.1 C413.1 C414.1 C445.2 C446.2 L47.2 L48.2 R247.1 R308.1 R324.2 R325.2 R326.2 R328.2 U18.16(VO) U20.15(IN1) U20.16(IN2) U20.17(IN3) U22.15(IN1) U22.16(IN2) U22.17(IN3) U23.15(IN1) U23.16(IN2) U23.17(IN3) U27.15(IN1) U27.16(IN2) U27.17(IN3) U29.15(IN1) U29.16(IN2) U29.17(IN3) ; also on sheet 2
+2.5VCLK: C433.1 C434.1 FB37.3 PP32.1 U32.3(SENSE) ; also on sheet 14
+3.3VCLK: C312.1 C313.1 FB17.3 PP1.1 U11.3(SENSE) ; also on sheet 14 15
+5VIN: C278.1 C301.1 C302.2 C303.1 C304.1 C305.1 C306.1 C307.2 C308.2 C343.2 C344.2 C438.2 C439.2 C440.1 C466.1 C467.1 C468.2 F1.2 JP9.1(Pin1) L49.1 Q24.1(S1) Q24.2(S2) Q24.3(S3) R208.2 R221.1 R246.2 R329.1 U4.1(VIN) U11.13(EN) U11.15(IN2) U11.16(IN1) U17.5(V+) U18.3(IN1) U18.8(MODE) U18.9(IN2) U19.5(V+) U21.5(V+) U24.5(V+) U28.5(V+) U30.5(V+) U32.15(IN2) U32.16(IN1) ; also on sheet 1 2 6 16
DVDD: C331.1 C332.1 FB20.3 FB38.3 PP5.1 R301.1 ; also on sheet 8
GND: C271.2 C272.2 C273.1 C274.1 C275.1 C276.1 C277.1 C278.2 C279.1 C280.2 C281.2 C282.2 C283.2 C284.1 C285.2 C286.1 C287.2 C288.2 C289.2 C290.2 C291.2 C292.2 C293.1 C294.2 C295.1 C296.2 C297.1 C298.2 C299.1 C300.2 C301.2 C302.1 C303.2 C304.2 C305.2 C306.2 C307.1 C308.1 C309.2 C310.2 C311.2 C312.2 C313.2 C314.2 C325.2 C326.2 C328.2 C329.1 C330.2 C331.2 C332.2 C333.2 C334.2 C335.1 C336.2 C337.2 C341.2 C343.1 C344.1 C345.1 C346.1 C347.2 C348.2 C349.2 C350.2 C351.2 C352.2 C353.2 C354.2 C355.2 C356.2 C357.2 C359.2 C360.2 C361.2 C362.2 C363.2 C364.2 C365.2 C366.2 C367.2 C368.2 C369.2 C370.2 C371.2 C372.2 C373.2 C374.2 C375.2 C376.2 C378.2 C379.2 C380.2 C381.2 C382.2 C383.2 C384.2 C385.2 C386.2 C387.2 C388.2 C389.2 C391.2 C392.2 C402.2 C403.2 C404.2 C405.2 C406.2 C407.2 C409.2 C410.2 C411.2 C412.2 C413.2 C414.2 C415.2 C416.2 C417.2 C418.2 C420.2 C421.2 C432.2 C433.2 C434.2 C435.2 C436.2 C437.2 C438.1 C439.1 C440.2 C443.2 C444.1 C445.1 C446.1 C447.2 C448.2 C449.2 C450.2 C451.2 C452.2 C453.2 C455.2 C456.2 C466.2 C467.2 C468.1 C501.2 D11.2(CATHODE) D12.2(CATHODE) FB13.2 FB17.2 FB19.2 FB20.2 FB21.2 FB22.2 FB23.2 FB24.2 FB25.2 FB26.2 FB27.2 FB28.2 FB29.2 FB30.2 FB31.2 FB32.2 FB34.2 FB35.2 FB36.2 FB37.2 FB38.2 J33.5(GND) J33.6(GND1) J33.7(GND2) J33.8(GND3) J33.9(GND4) J35.2 J35.3 JP9.3(Pin3) Q26.2(E) Q27.2(E) R214.2 R216.1 R222.1 R223.1 R224.1 R241.2 R243.2 R244.2 R248.2 R250.2 R252.1 R253.1 R254.1 R256.2 R258.1 R259.1 R260.1 R263.1 R264.2 R265.1 R266.1 R275.2 R276.1 R277.1 R278.1 R281.2 R282.1 R283.1 R284.1 R285.1 R297.1 R298.1 R299.1 R300.1 TP2.1(TP) U4.2(GND) U5.1(GND) U5.5(GND) U5.10(AGND) U5.11(GND) U5.13(TEST) U5.15(GND) U5.25(GND) U5.35(GND) U5.47(GND) U5.51(GND) U6.11(GND) U6.21(PWRPAD) U7.11(GND) U7.21(PWRPAD) U8.5(GND) U9.11(GND) U9.21(PWRPAD) U10.7(GND) U11.7(GND) U11.8(1P6V) U11.21(PWRPAD) U12.2(GND) U16.3(GND) U16.5(GND) U16.23(THERMPAD) U17.2(GND) U18.1(PGND1) U18.6(VSEL) U18.11(PGND2) U18.13(AGND) U19.2(GND) U20.8(GND) U20.18(GND) U20.21(THERMPAD) U21.2(GND) U22.8(GND) U22.18(GND) U22.21(THERMPAD) U23.8(GND) U23.18(GND) U23.21(THERMPAD) U24.2(GND) U27.8(GND) U27.18(GND) U27.21(THERMPAD) U28.2(GND) U29.8(GND) U29.18(GND) U29.21(THERMPAD) U30.2(GND) U32.7(GND) U32.21(PWRPAD) U33.7(GND) Y2.2 Y2.4 ; also on sheet 1 2 4 6 7 8 9 10 11 12 13 14 15 16
VDDA_1.0V: C365.1 C366.1 FB26.3 PP13.1 ; also on sheet 8
VDDA_1.8V: C382.1 C383.1 FB31.3 PP19.1 ; also on sheet 8 12 13
VDDA_SERDES_1.0V: C410.1 C411.1 FB35.3 PP26.1 ; also on sheet 8
VDDCLK_1.0V: C359.1 C360.1 FB24.3 PP11.1 ; also on sheet 8
VDDE: C325.1 C326.1 FB19.3 PP4.1 ; also on sheet 8
VDDGPIO_1.8V: C356.1 C357.1 FB23.3 PP10.1 ; also on sheet 6 8
VDDL1_1.0V: C348.1 C349.1 FB21.3 PP7.1 ; also on sheet 8
VDDL2_1.0V: C350.1 C351.1 FB22.3 PP9.1 ; also on sheet 8
VDDPLL_1.0V: C369.1 C370.1 FB28.3 PP15.1 ; also on sheet 8
VDDPLL_1.8V: C367.1 C368.1 FB27.3 PP14.1 ; also on sheet 8
VDDR_SERDES_1.5V: C416.1 C417.1 FB36.3 PP27.1 ; also on sheet 8
VDDT_SERDES_1.0V: C402.1 C403.1 FB34.3 PP24.1 ; also on sheet 8
VDDTX_1.0V: C376.1 C379.1 FB30.3 PP18.1 ; also on sheet 8
VDDTX_1.8V: C375.1 C378.1 FB29.1 PP17.1 ; also on sheet 8
VDDVCO_1.8V: C363.1 C364.1 FB25.3 PP12.1 ; also on sheet 8
BOOT: R235.2 U16.4(BOOT)
DACOUT: R321.2 ; also on sheet 6
DM: J33.2(D-) R211.1
DP: J33.3(D+) R212.1
EEDATA: R220.1 U5.61(EEDATA) U8.3(DI)
FMC_LMK_CS: U33.5(A4) ; also on sheet 16
FMC_LMK_SCK: U33.2(A1) ; also on sheet 16
FMC_LMK_SDIO: U33.3(A2) ; also on sheet 16
FMC_LMK_SDO: U33.4(A3) ; also on sheet 16
FTDI_DSASW (page SHEET 15 - USB I/F): U10.4(A3)
FTDI_FBBANDSEL (page SHEET 15 - USB I/F): U10.5(A4)
FTDI_FSPICLKA: U6.1(A1) ; also on sheet 7
FTDI_FSPICLKB: U6.4(A3) ; also on sheet 7
FTDI_FSPICLKC: U6.6(A5) ; also on sheet 7
FTDI_FSPICLKD: U6.8(A7) ; also on sheet 7
FTDI_FSPIDA: U6.3(A2) ; also on sheet 7
FTDI_FSPIDB: U6.5(A4) ; also on sheet 7
FTDI_FSPIDC: U6.7(A6) ; also on sheet 7
FTDI_FSPIDD: U6.9(A8) ; also on sheet 7
FTDI_RXDSAFAST (page SHEET 15 - USB I/F): U10.2(A1)
FTDI_RXFBNCO (page SHEET 15 - USB I/F): U10.3(A2)
FTDI_RXFBSW (page SHEET 15 - USB I/F): U9.9(A8)
FTDI_RXTDD_MODE (page SHEET 15 - USB I/F): U9.8(A7)
FTDI_SPIACLK: U7.3(A2) ; also on sheet 7
FTDI_SPIASDIO: U7.5(A4) ; also on sheet 7
FTDI_SPIASDO: U7.4(A3) ; also on sheet 7
FTDI_SPIASEN: U7.1(A1) ; also on sheet 7
FTDI_SPIBCLK: U7.7(A6) ; also on sheet 7
FTDI_SPIBSDIO: U7.9(A8) ; also on sheet 7
FTDI_SPIBSDO: U7.8(A7) ; also on sheet 7
FTDI_SPIBSEN: U7.6(A5) ; also on sheet 7
FTDI_TCK: U9.1(A1) ; also on sheet 7
FTDI_TDI: U9.3(A2) ; also on sheet 7
FTDI_TDO: U9.4(A3) ; also on sheet 7
FTDI_TMS: U9.5(A4) ; also on sheet 7
FTDI_TRSTB: U9.6(A5) ; also on sheet 7
FTDI_TXTDD_MODE (page SHEET 15 - USB I/F): U9.7(A6)
LMK_CS: J36.11 ; also on sheet 15
LMK_SCK: J36.2 ; also on sheet 15
LMK_SDIO: J36.5 ; also on sheet 15
LMK_SDO: J36.8 ; also on sheet 15
OSCI: C296.1 U5.2(OSCI) Y2.1
OSCO: C298.1 U5.3(OSCO) Y2.3
PG_2p2V: Q27.1(B) R273.2 R328.1 U18.5(PG)
PG_DVDD1P0V: R251.2 R326.1 U16.22(PG) U27.4(PG)
PG_RX1P2V: R257.2 R279.2 R325.1 U23.4(PG)
PG_TX1P0V: R261.2 R324.1 U20.4(PG)
PG_TX1P8V: R308.2 U22.4(PG) U29.4(PG) ; also on sheet 2
RX_1.2V: C388.1 C389.1 FB32.3 PP20.1 ; also on sheet 8
U16_FB: C340.2 R237.2 R239.2 R243.1 R245.2 R321.1 U16.2(FB)
U16_SW: C327.1 L46.1 R236.2 U16.6(SW1) U16.7(SW2) U16.8(SW3) U16.9(SW4) U16.10(SW5) U16.11(SW6)
USB_DM: C291.1 R211.2 U5.7(DM)
USB_DP: C290.1 R212.2 U5.8(DP)
USB_EECLK: R218.1 U5.62(EECLK) U8.2(CLK)
USB_EECS: R217.1 U5.63(EECS) U8.1(CS)
USB_REF: R214.1 U5.6(REF)
USB_RST: R215.2 U5.14(RESET)
N16791764: J33.1(VBUS) R210.2
N16791900: C282.1 C283.1 FB14.2 FB15.2 U5.4(VPHY)
N16791904: C271.1 C272.1 FB12.2 U5.9(VPLL)
N16792068: R213.2 R215.1 R216.2
N16792392: R219.1 R220.2 U8.4(DO)
N16935212: U5.21(ADBUS4) U6.15(B5)
N16935240: U5.16(ADBUS0) U6.20(B1)
N16935242: U5.18(ADBUS2) U6.17(B3)
N17033323: FB15.1 R209.1
N17033325: D11.1(ANODE) R209.2
N17828171: C280.1 C281.1 FB13.1 U4.5(VOUT)
N17829143: R208.1 U4.3(EN)
N18051729: U5.38(CDBUS0) U9.20(B1)
N18051775: U5.39(CDBUS1) U9.18(B2)
N18051825: U5.40(CDBUS2) U9.17(B3)
N18051839: U5.41(CDBUS3) U9.16(B4)
N18332757: U5.23(ADBUS6) U6.13(B7)
N18554997: D12.1(ANODE) R221.2
N18555159: Q24.4(G) U12.4(GATE)
N18962088: C309.1 C310.1 C311.1 FB17.1 U11.1(OUT1) U11.20(OUT2)
N18962090: C314.1 U11.14(NR)
N18962122: R222.2 U11.12(0P1V)
N18962132: R223.2 U11.11(0P2V)
N18962213: R224.2 U11.10(0P4V)
N18963933: R252.2 U20.5(50mV)
N18963939: C353.1 C355.1 C451.1 RS3.2 U19.3(VIN+) U20.1(OUT1) U20.19(OUT2) U20.20(OUT3)
N18963949: C362.1 U20.12(BIAS)
N18963966: R253.2 U20.6(100mV)
N18963972: C358.1 U20.3(FB)
N18963976: R254.2 U20.7(200mV)
N18964074: PP8.1 R249.1 R250.1
N18964185: R249.2 U19.1(OUT)
N18964329: C361.1 U20.13(NR/SS)
N18992157: R282.2 U29.6(100mV)
N18992183: C415.1 C418.1 C456.1 RS8.2 U29.1(OUT1) U29.19(OUT2) U29.20(OUT3) U30.3(VIN+)
N18992193: C420.1 U29.12(BIAS)
N18992197: R283.2 U29.7(200mV)
N18992199: C419.1 U29.3(FB)
N18992209: R284.2 U29.9(400mV)
N18992243: PP28.1 R280.1 R281.1
N18992297: R280.2 U30.1(OUT)
N18992349: C421.1 U29.13(NR/SS)
N18994871: R285.2 U29.10(800mV)
N19007167: C333.1 C334.1 C335.2 C336.1 L49.2 R234.2 U16.12(VIN1) U16.13(VIN2) U16.14(VIN3) U16.15(VIN4) U16.16(VIN5) U16.17(VIN6)
N19009214: C328.1 R234.1 U16.20(VDD)
N19009493: C501.1 Q26.3(C) U16.21(EN/SS)
N19010016: C327.2 R235.1
N19010394: C337.1 C447.1 C448.1 L46.2 R240.1 RS2.2 U17.3(VIN+)
N19011517: PP6.1 R238.1 R241.1
N19011541: C330.1 C449.1 C450.1 FB19.1 FB20.1 FB38.1 RS2.1 U17.4(VIN-)
N19011602: R238.2 U17.1(OUT)
N19016825: C338.2 R237.1
N19016841: C338.1 R239.1 R240.2 R301.2
N19016961: C342.2 R245.1
N19016975: C340.1 C342.1 U16.1(COMP)
N19024858: C329.2 R236.1
N19030259: R244.1 U16.18(ILIM)
N19030918: C341.1 U16.19(BP)
N19402254: J36.10 U5.54(DDBUS3)
N19402263: J36.7 U5.53(DDBUS2)
N19402272: J36.4 U5.52(DDBUS1)
N19402281: J36.1 U5.48(DDBUS0)
N19403607: U5.17(ADBUS1) U6.18(B2)
N19403614: U5.19(ADBUS3) U6.16(B4)
N19403621: U5.22(ADBUS5) U6.14(B6)
N19403628: U5.24(ADBUS7) U6.12(B8)
N19407936: U5.43(CDBUS4) U9.15(B5)
N19409548: U5.26(BDBUS0) U7.20(B1)
N19409557: U5.27(BDBUS1) U7.18(B2)
N19409566: U5.28(BDBUS2) U7.17(B3)
N19409575: U5.29(BDBUS3) U7.16(B4)
N19410556: U5.30(BDBUS4) U7.15(B5)
N19410565: U5.32(BDBUS5) U7.14(B6)
N19410574: U5.33(BDBUS6) U7.13(B7)
N19410583: U5.34(BDBUS7) U7.12(B8)
N19463241: R251.1 U20.14(EN)
N19466012: R279.1 U29.14(EN)
N19512252: U5.44(CDBUS5) U9.14(B6)
N19512261: U5.45(CDBUS6) U9.13(B7)
N19512270: U5.46(CDBUS7) U9.12(B8)
N19520191: U5.55(DDBUS4) U10.10(B4)
N19520200: U5.57(DDBUS5) U10.11(B3)
N19525330: U5.59(DDBUS7) U10.13(B1)
N19525339: U5.58(DDBUS6) U10.12(B2)
N19898860: J36.3 U33.13(B1)
N19898869: J36.6 U33.12(B2)
N19898878: J36.9 U33.11(B3)
N19898887: J36.12 U33.10(B4)
N20070471: C435.1 C436.1 C437.1 FB37.1 U32.1(OUT1) U32.20(OUT2)
N20070473: C432.1 U32.14(NR)
N20070515: R298.2 U32.12(0P1V)
N20070523: R299.2 U32.11(0P2V)
N20070610: R297.2 U32.10(0P4V)
N20070750: R300.2 U32.9(0P8V)
N20073169: L48.1 U18.10(SW2)
N20073179: L47.1 U18.2(SW1)
N20073199: R247.2 R248.1 U18.14(FB)
N20073285: R246.1 U18.4(EN)
N20073325: C347.1 U18.12(SS/TR)
N20074418: R277.2 U27.5(50mV)
N20074438: C406.1 C407.1 C455.1 RS7.2 U27.1(OUT1) U27.19(OUT2) U27.20(OUT3) U28.3(VIN+)
N20074448: C412.1 U27.12(BIAS)
N20074452: R276.2 U27.6(100mV)
N20074454: C408.1 U27.3(FB)
N20074458: R278.2 U27.7(200mV)
N20074494: PP25.1 R274.1 R275.1
N20074551: R274.2 U28.1(OUT)
N20074589: C409.1 U27.13(NR/SS)
N20074804: R273.1 U27.14(EN)
N20081535: R258.2 U22.6(100mV)
N20081541: C373.1 C374.1 C452.1 RS4.2 U21.3(VIN+) U22.1(OUT1) U22.19(OUT2) U22.20(OUT3)
N20081551: C380.1 U22.12(BIAS)
N20081555: R259.2 U22.7(200mV)
N20081559: C377.1 U22.3(FB)
N20081580: R260.2 U22.10(800mV)
N20081656: PP16.1 R255.1 R256.1
N20081707: R255.2 U21.1(OUT)
N20081783: C381.1 U22.13(NR/SS)
N20082233: R257.1 U22.14(EN)
N20090664: R261.1 U23.14(EN)
N20090676: C386.1 C387.1 C453.1 RS5.2 U23.1(OUT1) U23.19(OUT2) U23.20(OUT3) U24.3(VIN+)
N20090711: R263.2 U23.5(50mV)
N20090727: C391.1 U23.12(BIAS)
N20090731: R265.2 U23.6(100mV)
N20090737: C390.1 U23.3(FB)
N20090741: R266.2 U23.9(400mV)
N20090777: PP21.1 R262.1 R264.1
N20090807: R262.2 U24.1(OUT)
N20090845: C392.1 U23.13(NR/SS)
N20203110: Q26.1(B) Q27.3(C) R329.2
N20382523: JP9.2(Pin2) U32.13(EN)

Not connected (* = marked no-connect by the designer): J33 4(ID)*; U4 4(NC); U5 36(SUSPEND)* 60(PWREN)*; U8 7(NC)*; U10 6(NC1)* 9(NC2)*; U11 2(NC1)* 4(6P4V2)* 5(6P4V1)* 6(3P2V)* 9(0P8V)* 17(NC2)* 18(NC3)* 19(NC4)*; U12 1(NC1)* 3(NC3)*; U18 7(TG)* 15(RS)*; U20 9(400mV)* 10(800mV)* 11(1.6V)*; U22 5(50mV)* 9(400mV)* 11(1.6V)*; U23 7(200mV)* 10(800mV)* 11(1.6V)*; U27 9(400mV)* 10(800mV)* 11(1.6V)*; U29 5(50mV) 11(1.6V)*; U32 2(NC1)* 4(6P4V2)* 5(6P4V1)* 6(3P2V)* 8(1P6V)* 17(NC2)* 18(NC3)* 19(NC4)*; U33 6(NC1)* 9(NC2)*

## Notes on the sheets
sheet 18
- 1
- 2
sheet 19
- 2
- place on the same layer
  of device fo rminumum
  inductance
- 3
- place on the same layer
  of device for minumum
  inductance
sheet 20
- 4
- place on the same layer
  of device fo rminumum
  inductance
- 5
- place on the same layer
  of device fo rminumum
  inductance
- 5
- place on the same layer
  of device for minumum
  inductance
